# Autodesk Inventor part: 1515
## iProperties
Author: Administrator
Shininess: 55.0
PropertySet Name: _Private Model Information
Compacted: True
Length Units: 11272
Angle Units: 11286
Time Units: 11279
Mass Units: 11290
Length Display Precision: 3
Angle Display Precision: 2
Created: 2001-08
Part Number: 1515
Document SubType Name: Modeling
Designer: Administrator
Material: Aluminum-6105-T5
Description: 8020 #1515 T-Slot Extrusion
Control State: 0
Master: False
Checked Out: False
PropertySet Name: Design Tracking Control
Density: 2.71
Volumn: 95.83479759483512
Area: 506.52270580202696
PropertySet Name: Model Information
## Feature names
1. Core [Extrusion]
2. E1501 [Extrusion]
3. E1502 [Extrusion]
4. E1503 [Extrusion]
5. E1504 [Extrusion]
6. Divits [Extrusion]
7. MoreCores [Rectangular Pattern]
8. FillHoles [Extrusion]
9. Cuttout [Extrusion]
10. LargeFill [Extrusion]
11. LargeCut [Extrusion]
12. Cuttouts [Rectangular Pattern]
13. LargeCutouts [Rectangular Pattern]
14. 2xfFill [Extrusion]
15. 2xCut [Extrusion]
